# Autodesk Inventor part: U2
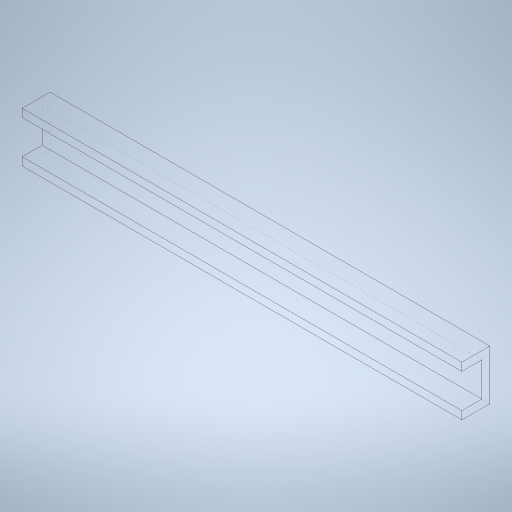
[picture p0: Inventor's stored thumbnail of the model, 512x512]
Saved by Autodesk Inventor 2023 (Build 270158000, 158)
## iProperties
Created: 2023-11
Part Number: U2
Material: Generic
Document SubType Name: Modeling
Designer: tornqvih
Density: 1 g/cm^3
Appearance: Default
Author: tornqvih
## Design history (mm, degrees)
sketch "Sketch1"
  geometry: L1 (6.25, 2.5)-(6.25, -4.5); L2 (6.25, -4.5)-(-6.25, -4.5); L3 (-6.25, -4.5)-(-6.25, 2.5); L4 (-6.25, 2.5)-(-4.25, 2.5); L5 (-4.25, 2.5)-(-4.25, -2.5); L6 (-4.25, -2.5)-(4.25, -2.5); L7 (4.25, -2.5)-(4.25, 2.5); L8 (4.25, 2.5)-(6.25, 2.5); L9 (0, -5.9)-(0, 3.9) reference; L10 (-8.75, 0)-(8.75, 0) reference; 1 further point
  constraints: 16 end point, 5 symmetric about line, 2 vertical, 1 horizontal alignment, 1 point on line
  dimensions: "d0" = 5 distance of L6.end L7.end; "d1" = 2 distance between parallel lines of L1 L7; "d2" = 2 distance between parallel lines of L2 L6; "d3" = 8.5 distance of L5.end L6.end
extrude "Extrusion1" new body sketch "Sketch1" distance "d4" = 110; taper "d5" = 0 deg
body "Solid1"
